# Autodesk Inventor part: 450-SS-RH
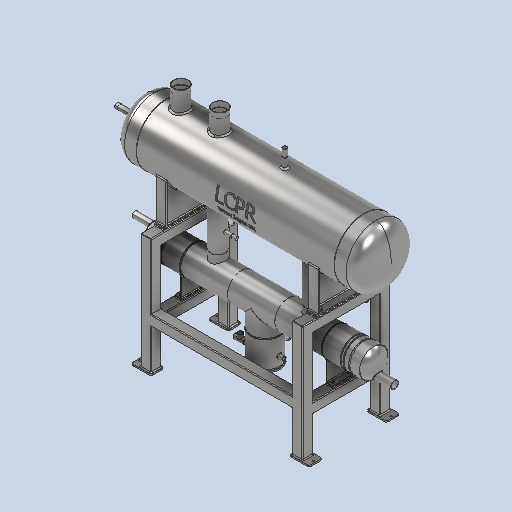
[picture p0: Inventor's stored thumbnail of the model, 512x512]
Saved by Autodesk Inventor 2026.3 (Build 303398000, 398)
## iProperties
Created: 2026-05
Part Number: 450-SS-RH
Material: Generic
Document SubType Name: Modeling
Designer: rva
Density: 1 g/cm^3
Appearance: Default
Author: rva
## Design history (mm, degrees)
derived "LCPR-SS-450-1500-100-SC-200-100-1370-48-50-40-RH-WELDED.iam"
body "Solid1"
feature "ⴒ"
node "Nylon Heat Tranfer Spacer 175x50.ipt:1"
node "Nylon Heat Tranfer Spacer 175x50.ipt:2"
node "Nylon Heat Tranfer Spacer 460x75.ipt:1"
node "Nylon Heat Tranfer Spacer 460x75.ipt:2"
node "Sub-SS-200-100-1370-48-10-50-40-RH-WELD.iam:1::LCPR-200 SS B"
node "Sub-SS-200-100-1370-48-10-50-40-RH-WELD.iam:1::DIN 2462 Tube"
node "Sub-SS-200-100-1370-48-10-50-40-RH-WELD.iam:1::DIN 2462 Tube"
node "Sub-SS-200-100-1370-48-10-50-40-RH-WELD.iam:1::DIN 2462 Tube"
node "Sub-SS-200-100-1370-48-10-50-40-RH-WELD.iam:1::DIN 2462 Tube"
node "Sub-SS-200-100-1370-48-10-50-40-RH-WELD.iam:1::DIN 2462 Tube"
node "Sub-SS-200-100-1370-48-10-50-40-RH-WELD.iam:1::DIN 2462 Tube"
node "Sub-SS-200-100-1370-48-10-50-40-RH-WELD.iam:1::DIN 2462 Tube"
node "Sub-SS-200-100-1370-48-10-50-40-RH-WELD.iam:1::DIN 2462 Tube"
node "Sub-SS-200-100-1370-48-10-50-40-RH-WELD.iam:1::DIN 2462 Tube"
node "Sub-SS-200-100-1370-48-10-50-40-RH-WELD.iam:1::DIN 2462 Tube"
node "Sub-SS-200-100-1370-48-10-50-40-RH-WELD.iam:1::DIN 2462 Tube"
node "Sub-SS-200-100-1370-48-10-50-40-RH-WELD.iam:1::DIN 2462 Tube"
node "Sub-SS-200-100-1370-48-10-50-40-RH-WELD.iam:1::SS-200 mm Sub"
node "Sub-SS-200-100-1370-48-10-50-40-RH-WELD.iam:1::SS-200 mm Sub"
node "Sub-SS-200-100-1370-48-10-50-40-RH-WELD.iam:1::DIN 2462 Tube"
node "Sub-SS-200-100-1370-48-10-50-40-RH-WELD.iam:1::DIN 2462 Tube"
node "Sub-SS-200-100-1370-48-10-50-40-RH-WELD.iam:1::DIN 2462 Tube"
node "Sub-SS-200-100-1370-48-10-50-40-RH-WELD.iam:1::DIN 2462 Tube"
node "Sub-SS-200-100-1370-48-10-50-40-RH-WELD.iam:1::H1100-R.ipt:1"
node "Sub-SS-200-100-1370-48-10-50-40-RH-WELD.iam:1::H1100-R.ipt:2"
node "Sub-SS-200-100-1370-48-10-50-40-RH-WELD.iam:1::1-2 Inch NPT "
node "Sub-SS-200-100-1370-48-10-50-40-RH-WELD.iam:1::3-4 Inch NPT "
node "Sub-SS-200-100-1370-48-10-50-40-RH-WELD.iam:1::1-2 Inch NPT "
node "Sub-SS-200-100-1370-48-10-50-40-RH-WELD.iam:1::Welds"
node "LCPR-SS-450-1500-100-WELD.iam:1::H1100-R.ipt:1"
node "LCPR-SS-450-1500-100-WELD.iam:1::450 mm SS Dome Cap.ipt:1"
node "LCPR-SS-450-1500-100-WELD.iam:1::450 mm SS Dome Cap.ipt:2"
node "LCPR-SS-450-1500-100-WELD.iam:1::Welds"
node "AS 1112 (2) - Metric M16  Type 10:1"
node "AS 1237 (4.1) 16 mm:1"
node "AS 1237 (4.1) 16 mm:2"
node "AS 1112 (2) - Metric M16  Type 10:2"
node "AS 1237 (4.1) 16 mm:3"
node "AS 1237 (4.1) 16 mm:4"
node "AS 1252 - Metric M16 x 120:2"
node "AS 1112 (2) - Metric M16  Type 10:3"
node "AS 1237 (4.1) 16 mm:5"
node "AS 1237 (4.1) 16 mm:6"
node "AS 1252 - Metric M16 x 120:3"
node "AS 1112 (2) - Metric M16  Type 10:4"
node "AS 1237 (4.1) 16 mm:7"
node "AS 1237 (4.1) 16 mm:8"
node "AS 1252 - Metric M16 x 120:4"
node "AS 1112 (2) - Metric M10  Type 10:1"
node "AS 1237 (D1) 10 mm:1"
node "AS 1237 (D1) 10 mm:2"
node "AS 1111 - Metric M10 x 120:1"
node "AS 1112 (2) - Metric M10  Type 10:2"
node "AS 1237 (D1) 10 mm:3"
node "AS 1237 (D1) 10 mm:4"
node "AS 1111 - Metric M10 x 120:2"
node "AS 1112 (2) - Metric M10  Type 10:3"
node "AS 1237 (D1) 10 mm:5"
node "AS 1237 (D1) 10 mm:6"
node "AS 1111 - Metric M10 x 120:3"
node "AS 1112 (2) - Metric M10  Type 10:4"
node "AS 1237 (D1) 10 mm:7"
node "AS 1237 (D1) 10 mm:8"
node "AS 1111 - Metric M10 x 120:4"
node "Welds"
node "AS 1252 - Metric M16 x 120:5"
node "LCPR-SS-450-1500-100-SC-200-100-1370-48-50-40-RH-WELDED.iam_"
